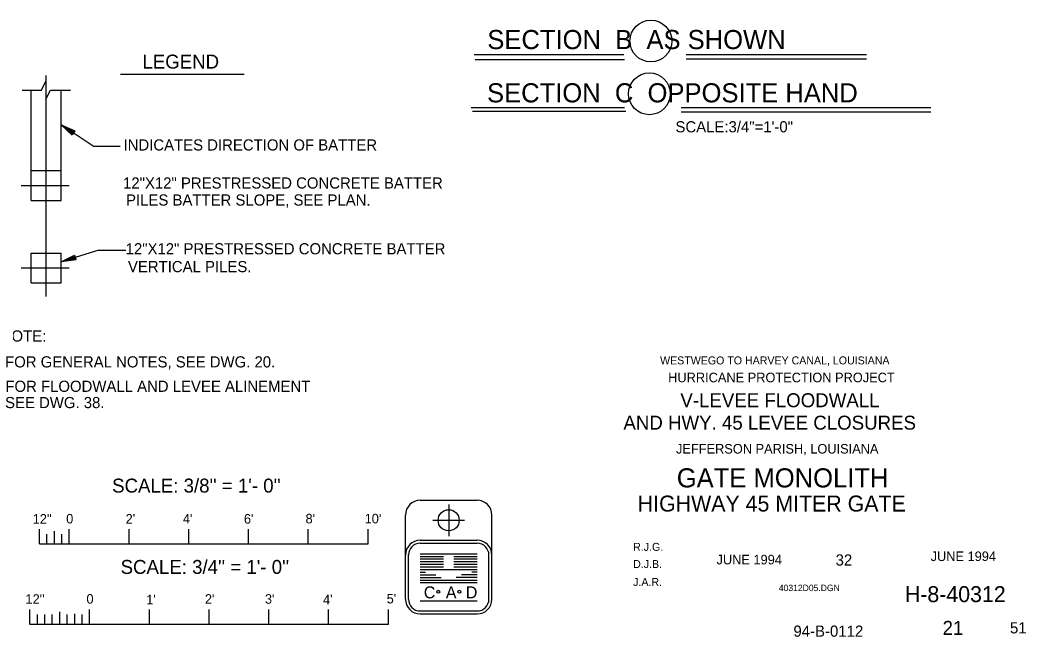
# Model space of a CAD drawing. Extents: x 6 to 106, y 3 to 74.
# Drawn here: x 72.23 to 105.9, y 2.99 to 23.63 of the extents above; entities that cross this region are included whole.
import ezdxf

# ---------------------------------------------------------------- set-up
doc = ezdxf.new("R2010")
doc.units = 0
for name, color, linetype in [('Level 1', 7, 'Continuous'), ('Level 13', 7, 'Continuous'), ('Level 2', 7, 'Continuous'), ('Level 22', 7, 'Continuous'), ('Level 25', 7, 'Continuous'), ('Level 3', 7, 'Continuous'), ('Level 50', 7, 'Continuous')]:
    doc.layers.add(name, color=color, linetype=linetype)

msp = doc.modelspace()

# ---------------------------------------------------------------- linework, layer by layer
at = {"layer": 'Level 1'}
for p, q in [((85.624, 7.559), (87.529, 7.559)), ((86.576, 7.418), (86.576, 6.362)), ((85.131, 4.25), (85.131, 7.066)), ((86.048, 6.89), (87.104, 6.89)), ((88.022, 4.25), (88.022, 7.066)), ((72.877, 6.098), (72.877, 6.598)), ((73.127, 6.098), (73.127, 6.431)), ((73.377, 6.098), (73.377, 6.521)), ((73.627, 6.098), (73.627, 6.431)), ((73.877, 6.098), (73.877, 6.598)), ((75.877, 6.098), (75.877, 6.598)), ((77.877, 6.098), (77.877, 6.598)), ((79.877, 6.098), (79.877, 6.598)), ((81.877, 6.098), (81.877, 6.598)), ((83.877, 6.098), (83.877, 6.598)), ((72.877, 6.098), (83.877, 6.098)), ((78.377, 6.098), (78.377, 6.098)), ((85.624, 6.221), (87.529, 6.221)), ((85.624, 6.123), (87.529, 6.123)), ((85.229, 4.25), (85.229, 5.729)), ((85.624, 5.771), (87.529, 5.771)), ((87.924, 4.25), (87.924, 5.729)), ((85.624, 5.683), (86.4, 5.683)), ((85.624, 5.595), (86.4, 5.595)), ((85.624, 5.507), (86.4, 5.507)), ((85.624, 5.419), (86.4, 5.419)), ((86.752, 5.683), (87.529, 5.683)), ((86.752, 5.595), (87.529, 5.595)), ((86.752, 5.507), (87.529, 5.507)), ((86.752, 5.419), (87.529, 5.419)), ((85.624, 5.331), (86.4, 5.331)), ((85.624, 5.243), (87.529, 5.243)), ((85.624, 5.155), (85.8, 5.155)), ((85.624, 5.067), (86.143, 5.067)), ((86.752, 5.331), (87.529, 5.331)), ((87.529, 5.067), (87.01, 5.067)), ((87.529, 5.155), (87.353, 5.155)), ((85.624, 4.979), (86.323, 4.979)), ((85.624, 4.891), (87.529, 4.891)), ((85.624, 4.803), (87.529, 4.803)), ((87.529, 4.979), (86.829, 4.979)), ((85.624, 4.191), (87.533, 4.191)), ((72.559, 3.408), (72.559, 3.908)), ((72.809, 3.408), (72.809, 3.741)), ((73.059, 3.408), (73.059, 3.741)), ((73.309, 3.408), (73.309, 3.741)), ((73.559, 3.408), (73.559, 3.83)), ((73.809, 3.408), (73.809, 3.741)), ((74.059, 3.408), (74.059, 3.76)), ((74.059, 3.408), (74.059, 3.75)), ((74.309, 3.408), (74.309, 3.741)), ((74.559, 3.408), (74.559, 3.908)), ((76.559, 3.408), (76.559, 3.908)), ((78.559, 3.408), (78.559, 3.908)), ((80.559, 3.408), (80.559, 3.908)), ((82.559, 3.408), (82.559, 3.908)), ((84.559, 3.408), (84.559, 3.908)), ((85.624, 3.856), (87.529, 3.856)), ((85.624, 3.757), (87.529, 3.757)), ((72.559, 3.408), (84.559, 3.408))]:
    msp.add_line(p, q, dxfattribs=at)
for centre, radius in [((86.576, 6.89), 0.352), ((86.227, 4.497), 0.0493), ((86.933, 4.497), 0.0493)]:
    msp.add_circle(centre, radius, dxfattribs=at)
for centre, radius, start, end in [((85.624, 7.066), 0.493, 90, 180), ((87.529, 7.066), 0.493, 0, 90), ((85.624, 5.728), 0.493, 90, 180), ((85.624, 5.728), 0.394, 90, 180), ((87.529, 5.728), 0.493, 0, 90), ((87.529, 5.728), 0.394, 0, 90), ((85.624, 4.25), 0.493, 180, 270), ((85.624, 4.25), 0.394, 180, 270), ((87.529, 4.25), 0.493, 270, 360), ((87.529, 4.25), 0.394, 270, 360)]:
    msp.add_arc(centre, radius, start, end, dxfattribs=at)
at = {"layer": 'Level 13'}
msp.add_lwpolyline([(72.947, 21.289), (73.096, 21.589), (73.096, 20.99), (73.246, 21.289)], dxfattribs=at)
at = {"layer": 'Level 22'}
for p, q in [((87.428, 22.478), (92.444, 22.478)), ((87.461, 22.316), (92.461, 22.316)), ((94.527, 22.478), (100.56, 22.478)), ((94.527, 22.332), (100.56, 22.332)), ((73.101, 17.14), (73.101, 21.775)), ((75.593, 21.818), (79.736, 21.818)), ((72.3, 21.289), (72.947, 21.289)), ((72.601, 17.598), (72.601, 21.289)), ((73.246, 21.289), (73.917, 21.289)), ((73.601, 17.598), (73.601, 21.289)), ((87.328, 20.711), (92.461, 20.711)), ((87.378, 20.581), (92.511, 20.581)), ((94.361, 20.711), (102.71, 20.711)), ((94.361, 20.565), (102.71, 20.565)), ((74.681, 19.415), (73.601, 20.127)), ((74.681, 19.415), (75.576, 19.415)), ((73.101, 14.379), (73.101, 17.14)), ((72.601, 14.836), (72.601, 15.836)), ((74.871, 15.936), (73.601, 15.543)), ((73.601, 14.836), (73.601, 15.836)), ((74.871, 15.936), (75.766, 15.936))]:
    msp.add_line(p, q, dxfattribs=at)
at = {"layer": 'Level 25'}
for p, q in [((72.601, 18.598), (73.601, 18.598)), ((72.269, 18.098), (73.871, 18.098)), ((72.601, 17.598), (73.601, 17.598)), ((72.601, 15.836), (73.601, 15.836)), ((72.269, 15.336), (73.871, 15.336)), ((72.601, 14.836), (73.601, 14.836))]:
    msp.add_line(p, q, dxfattribs=at)
at = {"layer": 'Level 3'}
for centre in [(93.344, 22.931), (93.294, 21.165)]:
    msp.add_circle(centre, 0.7, dxfattribs=at)
at = {"layer": 'Level 50'}
for p, q in [((73.601, 20.127), (73.601, 20.127)), ((73.717, 20.05), (73.717, 20.05)), ((73.601, 15.543), (73.601, 15.543)), ((73.733, 15.584), (73.733, 15.584))]:
    msp.add_line(p, q, dxfattribs=at)
for points in [[(73.972, 19.783), (73.601, 20.127), (74.063, 19.921), (73.985, 19.803), (73.717, 20.05), (74.03, 19.911), (73.98, 19.835), (73.828, 19.977), (73.998, 19.9), (73.977, 19.869), (73.944, 19.901)], [(74.102, 15.611), (73.601, 15.543), (74.053, 15.769), (74.095, 15.634), (73.733, 15.584), (74.04, 15.738), (74.067, 15.651), (73.861, 15.624), (74.028, 15.706), (74.039, 15.67), (73.993, 15.665)]]:
    msp.add_lwpolyline(points, dxfattribs=at)

# ---------------------------------------------------------------- texts
at = {"layer": 'Level 1'}
for s, height, p in [("SCALE: 3/8'' = 1'- 0''", 0.46666, (75.311, 7.818)), ("12''", 0.32, (72.65, 6.777)), ('0', 0.32, (73.773, 6.783)), ("2'", 0.32, (75.764, 6.779)), ("4'", 0.32, (77.681, 6.783)), ("6'", 0.32, (79.722, 6.779)), ("8'", 0.32, (81.785, 6.786)), ("10'", 0.32, (83.763, 6.786)), ("SCALE: 3/4'' = 1'- 0''", 0.46666, (75.595, 5.096)), ("12''", 0.32, (72.411, 4.094)), ('0', 0.32, (74.452, 4.099)), ("1'", 0.32, (76.453, 4.076)), ("2'", 0.32, (78.416, 4.096)), ("3'", 0.32, (80.426, 4.097)), ("4'", 0.32, (82.37, 4.077)), ("5'", 0.32, (84.5, 4.107)), ('C', 0.401, (85.743, 4.277)), ('A', 0.401, (86.48, 4.274)), ('D', 0.401, (87.15, 4.277))]:
    msp.add_text(s, height=height, dxfattribs=at).set_placement(p)
at = {"layer": 'Level 2'}
for s, height, p in [('SECTION  B  AS SHOWN', 0.63999, (87.87, 22.661)), ('SECTION  C  OPPOSITE HAND', 0.63999, (87.86, 20.878)), ('WESTWEGO TO HARVEY CANAL, LOUISIANA', 0.26567, (93.653, 12.108)), ('HURRICANE PROTECTION PROJECT', 0.32, (93.923, 11.51)), ('V-LEVEE FLOODWALL', 0.46733, (94.331, 10.675)), ('AND HWY. 45 LEVEE CLOSURES', 0.46733, (92.425, 9.924)), ('JEFFERSON PARISH, LOUISIANA', 0.32, (94.186, 9.124)), ('GATE MONOLITH', 0.63999, (94.211, 7.99)), ('HIGHWAY 45 MITER GATE', 0.53432, (92.904, 7.183)), ('R.J.G.', 0.2657, (92.75, 5.868)), ('JUNE 1994', 0.32, (95.542, 5.414)), ('32', 0.3743, (99.527, 5.375)), ('JUNE 1994', 0.32, (102.708, 5.526)), ('D.J.B.', 0.2657, (92.75, 5.293)), ('J.A.R.', 0.2657, (92.75, 4.693)), ('40312D05.DGN', 0.21432, (97.628, 4.52)), ('H-8-40312', 0.5343, (101.845, 4.151)), ('94-B-0112', 0.3743, (98.115, 2.993)), ('21', 0.4673, (103.108, 3.055)), ('51', 0.3743, (105.364, 3.104))]:
    msp.add_text(s, height=height, dxfattribs=at).set_placement(p)
at = {"layer": 'Level 22'}
for s, height, p in [('LEGEND', 0.4667, (76.325, 22.009)), ('SCALE:3/4"=1\'-0"', 0.37333, (94.168, 19.875)), ('INDICATES DIRECTION OF BATTER', 0.37333, (75.692, 19.267)), ('12"X12" PRESTRESSED CONCRETE BATTER', 0.37333, (75.677, 17.993)), ('PILES BATTER SLOPE, SEE PLAN.', 0.37333, (75.778, 17.424)), ('12"X12" PRESTRESSED CONCRETE BATTER', 0.37333, (75.764, 15.792)), ('VERTICAL PILES.', 0.37333, (75.841, 15.195)), ('NOTE:', 0.3733, (71.582, 12.872)), ('FOR GENERAL NOTES, SEE DWG. 20.', 0.37333, (71.727, 12.006)), ('FOR FLOODWALL AND LEVEE ALINEMENT', 0.37333, (71.737, 11.189)), ('SEE DWG. 38.', 0.37333, (71.727, 10.644))]:
    msp.add_text(s, height=height, dxfattribs=at).set_placement(p)

doc.saveas('drawing.dxf')
